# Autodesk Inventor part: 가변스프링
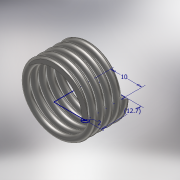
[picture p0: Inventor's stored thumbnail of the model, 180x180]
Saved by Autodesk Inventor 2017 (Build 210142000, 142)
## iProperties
Part Number: 가변스프링
Material: 스테인레스 스틸
Document SubType Name: Modeling
Designer: 00-00
Density: 8 g/cm^3
Appearance: 반연마
Mass: 7.63129 g
Surface Area: 19.5658 cm^2
Volume: 0.953911 cm^3
Author: 00-00
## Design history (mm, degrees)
sketch "스케치1"
  geometry: L1 (0, 0)-(10, 0); L2 (10, 0)-(10, 12.7); L3 (10, 12.7)-(0, 12.7); L4 (0, 12.7)-(0, 0); C1 r 1 at (10, 0)
  constraints: 8 end point, 2 parallel, 1 centre point, 1 coincident, 1 horizontal, 1 perpendicular
  dimensions: "d0" = 10 distance of L2.end L3.end; "d1" = 12.7 distance of L1.end L2.end (derived); "d2" = 2 diameter of C1
feature "코일1" pitch "d3" = 10; turns "d5" = 5; dims "d4" = 12.7 (= d1), "d6" = 0, angle "d7" = 90 deg, angle "d8" = 90 deg, "d9" = 0, "d10" = 0
sketch "스케치2"
  geometry: L1 (-9, 0)-(-11, 0) reference; 1 further point
  constraints: 1 horizontal alignment
extrude "돌출1" cut sketch "스케치2" distance "d11" = 10; taper "d12" = 0 deg
node "작업 평면1"
sketch "스케치3"
  geometry: L1 (-1, 0)-(1, 0) reference; 1 further point
  constraints: 1 horizontal alignment
extrude "돌출2" cut sketch "스케치3" distance "d14" = 10; taper "d15" = 0 deg
node "솔리드1"
node "절단 모서리 투영1"
node "절단 모서리 투영2"
other parameters: "d13" = 90 deg
